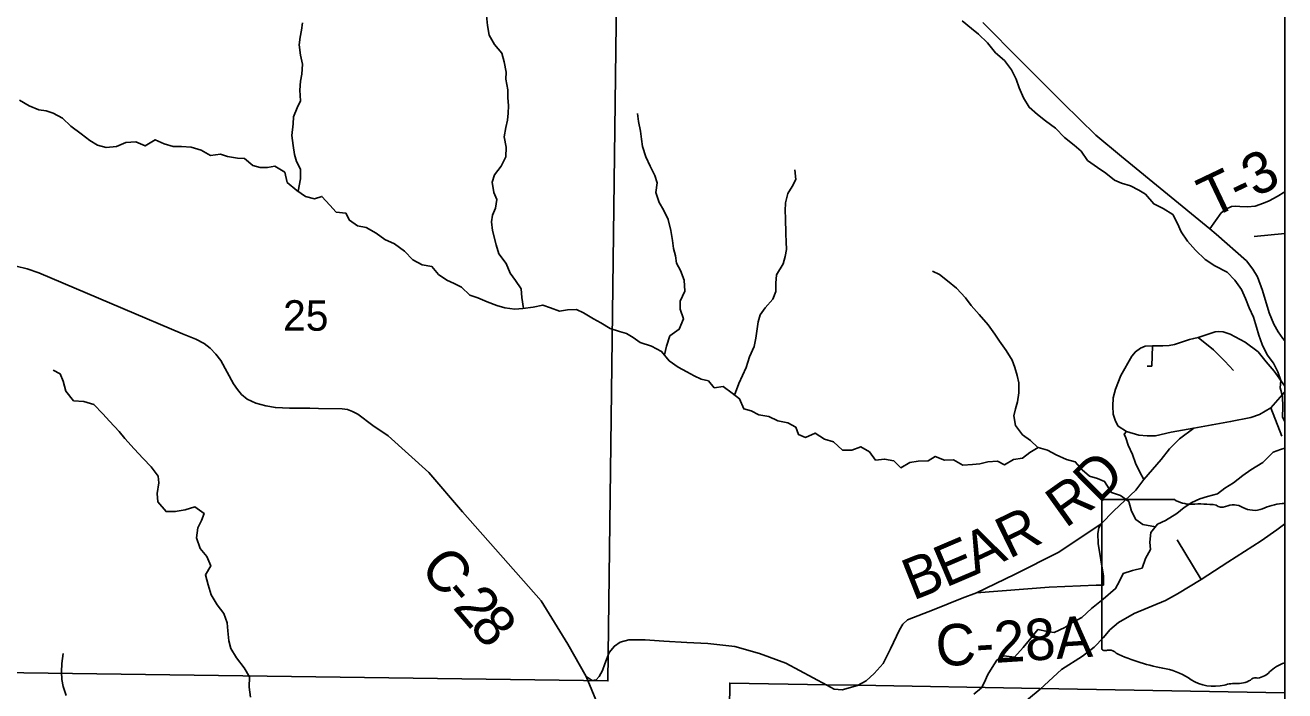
# Model space of a CAD drawing. Extents: x -3.6 to 34, y 0 to 32.8.
# Drawn here: x 1.441 to 3.17, y 28.937 to 29.85 of the extents above; entities that cross this region are included whole.
import ezdxf

# ---------------------------------------------------------------- set-up
doc = ezdxf.new("R2010")
doc.units = 0
for name, color, linetype in [('GM_X_Corporation', 7, 'Continuous'), ('GM_X_County_Road', 7, 'Continuous'), ('GM_X_County_Road_Text', 7, 'Continuous'), ('GM_X_Minor_River', 7, 'Continuous'), ('GM_X_Section_Text', 7, 'Continuous'), ('GM_X_State_Location', 7, 'Continuous'), ('GM_X_State_Route', 7, 'Continuous'), ('GM_X_State_Shield', 7, 'Continuous'), ('GM_X_Township_Road', 7, 'Continuous'), ('GM_X_Township_Road_Text', 7, 'Continuous'), ('SH_Data', 7, 'Continuous')]:
    doc.layers.add(name, color=color, linetype=linetype)

msp = doc.modelspace()

# ---------------------------------------------------------------- linework, layer by layer
at = {"layer": 'GM_X_Corporation'}
for points in [[(3.1705, 28.9337), (3.1705, 32.8429), (-3.6295, 32.8429), (-3.6295, 26.0429), (2.3706, 26.0429), (2.3712, 26.0804), (2.3716, 26.1248), (2.3732, 26.2253), (2.3789, 26.6097), (2.3911, 27.5117), (2.3952, 27.9336), (2.3997, 28.282), (2.4082, 28.9473), (2.5416, 28.945), (2.5837, 28.9442), (2.8343, 28.9397)], [(2.2535, 29.9602), (2.2411, 28.9502), (1.4051, 28.9619), (1.2386, 28.9647), (1.2483, 29.9822)], [(2.3706, 26.0429), (3.1705, 26.0429), (3.1705, 28.9337), (2.8343, 28.9397), (2.5837, 28.9442), (2.5416, 28.945), (2.4082, 28.9473), (2.3997, 28.282), (2.3952, 27.9336), (2.3911, 27.5117), (2.3789, 26.6097), (2.3732, 26.2253), (2.3716, 26.1248), (2.3712, 26.0804)], [(2.3706, 26.0429), (3.1705, 26.0429), (3.1705, 28.9337), (2.8343, 28.9397), (2.5837, 28.9442), (2.5416, 28.945), (2.4082, 28.9473), (2.3997, 28.282), (2.3952, 27.9336), (2.3911, 27.5117), (2.3789, 26.6097), (2.3732, 26.2253), (2.3716, 26.1248), (2.3712, 26.0804)]]:
    msp.add_lwpolyline(points, close=True, dxfattribs=at)
msp.add_lwpolyline([(-2.8635, 26.0429), (2.3706, 26.0429), (2.3712, 26.0804), (2.3716, 26.1248), (2.3732, 26.2253), (2.3789, 26.6097), (2.3911, 27.5117), (2.3952, 27.9336), (2.3997, 28.282), (2.4082, 28.9473), (2.5416, 28.945), (2.5837, 28.9442), (2.8343, 28.9397), (3.1705, 28.9337), (3.1705, 30.458), (3.0419, 30.4594), (1.7819, 30.4857), (1.2437, 30.4948), (0.4055, 30.5105), (0.3556, 30.5115), (0.2578, 30.5133), (0.2583, 30.5905), (-0.398, 30.5946), (-0.453, 30.5952)], dxfattribs=at)
at = {"layer": 'GM_X_County_Road'}
msp.add_line((2.9114, 29.0816), (2.9213, 29.0818), dxfattribs=at)
for points in [[(3.1705, 29.3468), (3.1514, 29.3247), (3.1356, 29.3156), (3.1236, 29.3116), (3.0961, 29.306), (3.0706, 29.3017), (3.0455, 29.2968), (3.026, 29.2822), (3.0121, 29.2687), (3.0009, 29.2541), (2.9767, 29.2268), (2.9658, 29.2119), (2.9358, 29.1834), (2.9183, 29.1659), (2.8604, 29.1267), (2.7993, 29.0964), (2.7472, 29.0711), (2.7273, 29.0639), (2.6891, 29.0481), (2.6526, 29.0339), (2.6461, 29.028), (2.6412, 29.0205), (2.629, 28.9944), (2.6189, 28.9739), (2.6064, 28.9604), (2.5956, 28.9503), (2.5839, 28.9437), (2.5627, 28.9378), (2.5518, 28.9388), (2.5418, 28.9445), (2.4855, 28.9746), (2.4493, 28.9878), (2.4153, 28.9972), (2.3781, 29.0014), (2.3494, 29.003), (2.3176, 29.0048), (2.2921, 29.0064), (2.2698, 29.0064), (2.2579, 29.0034), (2.25, 28.9981), (2.2426, 28.989), (2.2367, 28.9736), (2.2337, 28.9644), (2.229, 28.9562), (2.2247, 28.9518), (2.2193, 28.951), (2.2112, 28.9561), (2.1861, 29.0005), (2.1493, 29.0599), (2.0415, 29.1821), (1.9951, 29.2364), (1.9392, 29.2865), (1.9182, 29.3005), (1.8978, 29.3163), (1.8904, 29.3201), (1.8835, 29.3228), (1.8763, 29.3237), (1.8435, 29.3239), (1.8317, 29.3243), (1.8036, 29.3245), (1.7844, 29.3253), (1.7712, 29.3275), (1.7574, 29.3313), (1.7456, 29.337), (1.7381, 29.3432), (1.7323, 29.3502), (1.727, 29.3579), (1.7093, 29.3897), (1.7026, 29.3986), (1.6948, 29.4069), (1.6868, 29.413), (1.6753, 29.4191), (1.6567, 29.4265), (1.575, 29.4611), (1.4595, 29.5103), (1.4436, 29.5156), (1.4286, 29.5194)], [(2.7472, 29.0711), (2.8471, 29.0789), (2.9114, 29.0816)]]:
    msp.add_lwpolyline(points, dxfattribs=at)
at = {"layer": 'GM_X_Minor_River'}
for points in [[(1.8157, 29.622), (1.8189, 29.6389), (1.8187, 29.6526), (1.8133, 29.6627), (1.8105, 29.6725), (1.8087, 29.685), (1.807, 29.6987), (1.8087, 29.7146), (1.8093, 29.7241), (1.8144, 29.7367), (1.8188, 29.7463), (1.8178, 29.7606), (1.8191, 29.7732), (1.8205, 29.7827), (1.8218, 29.7964), (1.819, 29.8088), (1.8172, 29.8232), (1.8186, 29.8335), (1.8203, 29.843), (1.8217, 29.8533)], [(2.1249, 29.4612), (2.1226, 29.4762), (2.122, 29.4883), (2.1139, 29.4996), (2.1066, 29.5097), (2.1015, 29.5229), (2.0914, 29.536), (2.0874, 29.5485), (2.0826, 29.5681), (2.0813, 29.5799), (2.0827, 29.5894), (2.0867, 29.5989), (2.0884, 29.6107), (2.0844, 29.6205), (2.0823, 29.6345), (2.0852, 29.6444), (2.0945, 29.6563), (2.1007, 29.6693), (2.1013, 29.6826), (2.0984, 29.6966), (2.1009, 29.7095), (2.103, 29.7194), (2.104, 29.7293), (2.1046, 29.7395), (2.1037, 29.7505), (2.1035, 29.7611), (2.101, 29.7759), (2.1012, 29.7854), (2.0987, 29.7998), (2.0952, 29.8115), (2.0855, 29.8235), (2.0781, 29.8362), (2.0757, 29.8495), (2.0743, 29.8631)], [(3.1705, 29.3059), (3.1672, 29.3124), (3.1678, 29.326), (3.1675, 29.3408), (3.1643, 29.3525), (3.1649, 29.3624), (3.161, 29.3741), (3.1551, 29.3861), (3.1462, 29.3978), (3.1396, 29.4117), (3.1349, 29.4245), (3.1317, 29.4355), (3.1277, 29.4495), (3.1214, 29.4623), (3.1163, 29.4747), (3.1108, 29.4871), (3.1019, 29.5003), (3.0915, 29.5111), (3.0744, 29.5196), (3.061, 29.5285), (3.0479, 29.5412), (3.0368, 29.5535), (3.0283, 29.5663), (3.0232, 29.578), (3.0165, 29.5904), (3.0035, 29.5986), (2.9906, 29.6048), (2.9794, 29.6179), (2.9699, 29.6235), (2.9584, 29.6294), (2.9463, 29.6333), (2.9364, 29.6374), (2.9245, 29.6471), (2.9134, 29.6545), (2.8996, 29.6645), (2.8907, 29.6773), (2.8811, 29.6855), (2.8681, 29.6959), (2.8554, 29.7086), (2.842, 29.7186), (2.8309, 29.7276), (2.8194, 29.7373), (2.8116, 29.7504), (2.8058, 29.764), (2.8014, 29.7761), (2.7952, 29.7889), (2.7855, 29.8013), (2.7732, 29.8121), (2.7621, 29.8256), (2.7498, 29.8375), (2.7402, 29.8453), (2.7275, 29.8561)], [(1.8592, 29.6031), (1.8484, 29.6151), (1.8379, 29.6119), (1.8257, 29.6151), (1.8139, 29.6233), (1.8008, 29.6341), (1.7972, 29.6481), (1.7838, 29.6566), (1.7736, 29.6549), (1.7634, 29.6548), (1.7535, 29.6573), (1.742, 29.667), (1.7322, 29.6676), (1.7185, 29.6696), (1.709, 29.6729), (1.6954, 29.6712), (1.6825, 29.6786), (1.6688, 29.6825), (1.6555, 29.6835), (1.6442, 29.6837), (1.6316, 29.6873), (1.6194, 29.6928), (1.6056, 29.6842), (1.593, 29.6897), (1.579, 29.6888), (1.5662, 29.6836), (1.5522, 29.6819), (1.5401, 29.6855), (1.5298, 29.6918), (1.5175, 29.7007), (1.5037, 29.7115), (1.4922, 29.7224), (1.4792, 29.7294), (1.4697, 29.7326), (1.4595, 29.734), (1.4462, 29.7391), (1.4332, 29.7469)], [(2.3186, 29.3977), (2.3215, 29.4093), (2.3262, 29.4235), (2.3389, 29.4327), (2.3448, 29.4472), (2.3404, 29.4605), (2.3403, 29.4711), (2.3465, 29.4852), (2.3459, 29.5), (2.3407, 29.5132), (2.3353, 29.5233), (2.3336, 29.5336), (2.3312, 29.5434), (2.3299, 29.5544), (2.3274, 29.5684), (2.3238, 29.5831), (2.3175, 29.5967), (2.3113, 29.6068), (2.3066, 29.6204), (2.3086, 29.6337), (2.3055, 29.6435), (2.2992, 29.6567), (2.2933, 29.6691), (2.2886, 29.6835), (2.2873, 29.6937), (2.2856, 29.7047), (2.2828, 29.7179), (2.2818, 29.7289)], [(2.4149, 29.3424), (2.4207, 29.3581), (2.4309, 29.3803), (2.4356, 29.3951), (2.4418, 29.4092), (2.444, 29.4203), (2.4457, 29.4302), (2.4474, 29.4431), (2.4503, 29.4526), (2.4569, 29.4622), (2.4673, 29.4741), (2.4714, 29.4844), (2.4716, 29.4958), (2.4725, 29.5076), (2.4817, 29.5225), (2.4846, 29.5324), (2.4864, 29.5423), (2.4858, 29.5525), (2.4853, 29.5635), (2.485, 29.5851), (2.4844, 29.595), (2.485, 29.6064), (2.4882, 29.6189), (2.4941, 29.6285), (2.4989, 29.6384), (2.4979, 29.6513)], [(2.993, 29.1618), (2.9757, 29.165), (2.9658, 29.1716), (2.9599, 29.1833), (2.9563, 29.1962), (2.9448, 29.2047), (2.9323, 29.2087), (2.923, 29.2237), (2.9131, 29.2278), (2.9021, 29.231), (2.8921, 29.24), (2.8828, 29.2508), (2.8707, 29.254), (2.8566, 29.2603), (2.8444, 29.2666), (2.8318, 29.2705), (2.8202, 29.2635), (2.8105, 29.2558), (2.798, 29.2541), (2.7856, 29.2467), (2.7761, 29.2519), (2.7629, 29.2509), (2.7519, 29.2481), (2.7417, 29.2472), (2.7285, 29.2462), (2.7155, 29.2536), (2.7034, 29.2531), (2.6905, 29.2582), (2.6807, 29.2523), (2.6671, 29.2518), (2.6554, 29.2501), (2.643, 29.2427), (2.6334, 29.252), (2.6209, 29.2545), (2.6085, 29.2532), (2.6003, 29.2644), (2.5881, 29.2715), (2.5761, 29.2667), (2.5632, 29.2669), (2.5509, 29.2781), (2.5384, 29.2817), (2.5254, 29.2902), (2.5122, 29.2844), (2.5027, 29.2884), (2.4992, 29.2982), (2.4881, 29.3041), (2.4744, 29.3069), (2.4619, 29.3132), (2.4482, 29.3153), (2.4375, 29.3208), (2.4276, 29.3237), (2.4218, 29.3373), (2.4114, 29.3451), (2.3992, 29.354), (2.3871, 29.3523), (2.379, 29.362), (2.3691, 29.3642), (2.3596, 29.3686), (2.3493, 29.3745), (2.3375, 29.3808), (2.3252, 29.3893), (2.3148, 29.4024), (2.3007, 29.4094), (2.2855, 29.4145), (2.2759, 29.4216), (2.2664, 29.4271), (2.2569, 29.4296), (2.2443, 29.4336), (2.2313, 29.4414), (2.221, 29.4469), (2.2077, 29.4551), (2.1981, 29.4599), (2.1853, 29.4593), (2.1747, 29.4576), (2.1622, 29.462), (2.1515, 29.466), (2.1383, 29.4631), (2.124, 29.461), (2.1134, 29.4605), (2.0993, 29.4622), (2.0883, 29.4654), (2.0754, 29.4705), (2.0624, 29.476), (2.0514, 29.4797), (2.0399, 29.4905), (2.03, 29.4953), (2.0197, 29.5), (2.0086, 29.5078), (1.9993, 29.5187), (1.9861, 29.5212), (1.9731, 29.5282), (1.9616, 29.5398), (1.9478, 29.5498), (1.9348, 29.5561), (1.923, 29.5646), (1.9092, 29.5724), (1.8971, 29.5745), (1.8864, 29.5823), (1.8813, 29.592), (1.8677, 29.5934), (1.8592, 29.6031)], [(2.8314, 29.2703), (2.8211, 29.2802), (2.8104, 29.288), (2.8007, 29.3008), (2.7986, 29.314), (2.8007, 29.3236), (2.8036, 29.3331), (2.8053, 29.3456), (2.8051, 29.3593), (2.8031, 29.3695), (2.7999, 29.3801), (2.7959, 29.3902), (2.7878, 29.4038), (2.7789, 29.4162), (2.7723, 29.4259), (2.763, 29.4387), (2.7507, 29.4529), (2.7396, 29.4653), (2.7318, 29.4758), (2.7195, 29.4889), (2.7073, 29.4993), (2.6961, 29.5079), (2.6866, 29.5126)], [(1.7503, 28.9281), (1.7482, 28.9418), (1.7487, 28.9558), (1.7417, 28.9682), (1.7309, 28.9817), (1.7232, 28.9949), (1.7207, 29.0051), (1.719, 29.0191), (1.7181, 29.0301), (1.7134, 29.0425), (1.7045, 29.0545), (1.6963, 29.0681), (1.6919, 29.082), (1.6883, 29.0956), (1.6957, 29.1079), (1.6902, 29.1211), (1.681, 29.1319), (1.6762, 29.1467), (1.6779, 29.1603), (1.683, 29.1703), (1.6867, 29.1798), (1.674, 29.1891), (1.6605, 29.1851), (1.6469, 29.1826), (1.6344, 29.1825), (1.6232, 29.1959), (1.6219, 29.2073), (1.6243, 29.2218), (1.6234, 29.2312), (1.6138, 29.244), (1.603, 29.2552), (1.5903, 29.2687), (1.5776, 29.2829), (1.5699, 29.2926), (1.5565, 29.3065), (1.5476, 29.3166), (1.5349, 29.3293), (1.5212, 29.3336), (1.5072, 29.3345), (1.4968, 29.3477), (1.4932, 29.3616), (1.4889, 29.3714), (1.4793, 29.3766)], [(3.1705, 29.2696), (3.1645, 29.2676), (3.1547, 29.264), (3.1405, 29.2501), (3.1237, 29.24), (3.1128, 29.2319), (3.1001, 29.2222), (3.0881, 29.2148), (3.078, 29.2067), (3.0644, 29.2031), (3.0539, 29.1999), (3.0426, 29.1952), (3.0321, 29.1882), (3.0224, 29.1797), (3.0067, 29.1704), (2.9958, 29.1653), (2.9865, 29.1538), (2.9852, 29.1408), (2.9861, 29.1306), (2.9791, 29.1184), (2.9744, 29.105), (2.9615, 29.1018), (2.9484, 29.0974), (2.9436, 29.0871), (2.9381, 29.0768), (2.9209, 29.0625), (2.9052, 29.0497), (2.8918, 29.037), (2.8782, 29.03), (2.8685, 29.0234), (2.8539, 29.0167), (2.8444, 29.0181), (2.8315, 29.0209), (2.8222, 29.0094), (2.811, 28.996), (2.7995, 28.9829), (2.7847, 28.9846), (2.775, 28.9787), (2.7687, 28.9688), (2.7628, 28.9588), (2.7576, 28.9478), (2.7539, 28.9409)], [(1.4971, 28.9304), (1.4931, 28.9425), (1.4911, 28.9523), (1.4909, 28.9625), (1.4911, 28.9739), (1.4932, 28.9876)], [(2.7436, 28.9322), (2.7539, 28.9409)]]:
    msp.add_lwpolyline(points, dxfattribs=at)
at = {"layer": 'GM_X_State_Route'}
for points in [[(3.1705, 29.4169), (3.1679, 29.42), (3.1612, 29.4292), (3.1555, 29.4395), (3.1489, 29.4552), (3.1399, 29.4858), (3.1328, 29.5045), (3.1266, 29.5152), (3.1177, 29.5268), (3.0762, 29.5633), (3.0677, 29.5707), (2.9462, 29.6699), (2.9109, 29.6991), (2.8663, 29.7429), (2.8077, 29.8013), (2.7556, 29.8537)], [(2.8345, 28.9391), (2.8637, 28.9659), (2.8928, 28.9842), (2.9088, 28.9967), (2.9216, 29.0098), (2.9302, 29.0201), (2.9421, 29.0305), (2.9635, 29.0427), (3.0066, 29.0606), (3.023, 29.0696), (3.0557, 29.0893), (3.0924, 29.1132), (3.1378, 29.1425), (3.1593, 29.1577), (3.1705, 29.1656)], [(2.7996, 28.9101), (2.8345, 28.9391)]]:
    msp.add_lwpolyline(points, dxfattribs=at)
at = {"layer": 'GM_X_State_Shield'}
for p, q in [((3.0189, 29.199), (2.9223, 29.199)), ((2.9191, 29.1955), (2.9191, 28.9954)), ((3.1705, 28.975), (3.1705, 29.194))]:
    msp.add_line(p, q, dxfattribs=at)
for centre, major_axis, start_param, end_param in [((2.9229, 29.196), (0.00382, 0), 1.727492, 3.291633), ((3.0418, 29.2222), (0.037, 0), 4.042888, 4.731792), ((3.0541, 29.0866), (0.133, 0), 1.404758, 1.657859), ((3.0843, 29.197), (0.0107, 0), 3.836095, 5.185415), ((3.1, 29.1739), (0.0222, 0), 0.950623, 2.079405), ((3.1287, 29.2056), (0.0267, 0), 4.08156, 5.145723), ((3.1758, 29.1379), (0.0703, 0), 1.699012, 2.107814), ((3.1313, 29.4718), (0.3495, 0), 4.814394, 4.824795), ((2.9229, 28.995), (0.00385, 0), 2.993084, 4.5083), ((2.9235, 29.0155), (0.0294, 0), 4.665946, 4.897461), ((2.9295, 28.9839), (0.0106, 0), 0.519207, 1.627899), ((3.0633, 29.1637), (0.2524, 0), 4.195997, 4.488961), ((3.1877, 28.9392), (0.0479, 0), 1.939048, 2.488434), ((2.9881, 28.9055), (0.079, 0), 0.823519, 1.323587), ((3.1302, 28.9485), (0.00752, 0), 1.147584, 2.315152), ((3.127, 28.976), (0.0282, 0), 4.937069, 5.64225), ((3.0735, 28.9829), (0.0501, 0), 4.026481, 4.996735), ((3.1024, 28.9137), (0.0412, 0), 1.495662, 1.94098), ((3.1061, 28.9679), (0.0267, 0), 4.691044, 5.507374)]:
    msp.add_ellipse(centre, major_axis=major_axis, ratio=0.8, start_param=start_param, end_param=end_param, dxfattribs=at)
at = {"layer": 'GM_X_Township_Road'}
for p, q in [((3.1705, 29.5642), (3.1284, 29.5601)), ((3.1666, 29.286), (3.1514, 29.3247)), ((3.0557, 29.0893), (3.0225, 29.1438))]:
    msp.add_line(p, q, dxfattribs=at)
for points in [[(3.0677, 29.5707), (3.0831, 29.5925), (3.0894, 29.5975), (3.0971, 29.6013), (3.1026, 29.6018), (3.1085, 29.6013), (3.1191, 29.6007), (3.1297, 29.6018), (3.1411, 29.6057), (3.1491, 29.609), (3.1602, 29.6148), (3.1705, 29.6214)], [(3.0455, 29.2968), (3.0142, 29.2915), (2.9931, 29.2867), (2.9816, 29.2865), (2.9702, 29.2875), (2.9533, 29.2926), (2.9415, 29.2999), (2.9378, 29.3068), (2.9349, 29.316), (2.9343, 29.3273), (2.9348, 29.3386), (2.9379, 29.3505), (2.9453, 29.3693), (2.9603, 29.3959), (2.9653, 29.4018), (2.9725, 29.407), (2.9788, 29.4095), (2.9886, 29.4099), (3.0029, 29.4101), (3.0115, 29.4106), (3.0191, 29.412), (3.0243, 29.4135), (3.0396, 29.4188), (3.0455, 29.4202), (3.0516, 29.4216), (3.075, 29.4292), (3.0799, 29.4295), (3.0858, 29.4292), (3.0956, 29.426), (3.1159, 29.415), (3.1338, 29.4016), (3.1451, 29.3882), (3.156, 29.3754), (3.1705, 29.3545)], [(3.0998, 29.3761), (3.0883, 29.389), (3.0726, 29.4045), (3.0516, 29.4216)], [(2.9817, 29.3823), (2.9877, 29.3823), (2.9886, 29.4099)], [(2.9767, 29.2268), (2.9708, 29.2376), (2.9653, 29.2492), (2.9614, 29.2608), (2.9553, 29.2738), (2.952, 29.2836), (2.95, 29.2886), (2.9533, 29.2926)], [(2.9213, 29.0818), (2.9217, 29.0941), (2.9141, 29.1387), (2.9139, 29.1523), (2.9153, 29.1602), (2.9183, 29.1659)], [(2.2112, 28.9561), (2.2367, 28.8943), (2.2565, 28.8547), (2.2672, 28.8262), (2.2846, 28.7852), (2.2881, 28.7671), (2.2888, 28.7081), (2.2774, 28.6424), (2.2812, 28.5756), (2.2741, 28.5386), (2.2578, 28.5029), (2.2549, 28.4915), (2.2513, 28.4756), (2.2597, 28.4398), (2.2593, 28.4174), (2.261, 28.4022), (2.2681, 28.3872), (2.2764, 28.376), (2.2905, 28.3608), (2.3111, 28.3286)]]:
    msp.add_lwpolyline(points, dxfattribs=at)
at = {"layer": 'SH_Data'}
msp.add_line((3.1705, 32.8429), (3.1705, 26.0429), dxfattribs=at)

# ---------------------------------------------------------------- texts
at = {"layer": 'GM_X_County_Road_Text'}
for s, height, rotation, p in [('D', 0.0568, 44.8007, (2.9146, 29.1924)), ('R', 0.0568, 35.6146, (2.8692, 29.1589)), ('R', 0.0568, 25.9888, (2.7918, 29.1172)), ('E', 0.0568, 23.0721, (2.7046, 29.0779)), ('A', 0.0568, 25.2482, (2.7459, 29.0955)), ('C', 0.0568, 310.7431, (1.981, 29.1037)), ('B', 0.0568, 21.6666, (2.6599, 29.0601)), ('-', 0.0568, 310.7241, (2.0115, 29.0683)), ('2', 0.0568, 310.6261, (2.0267, 29.0507)), ('8', 0.0568, 310.1571, (2.0494, 29.0242)), ('C-28A', 0.05682, 3.6367, (2.6928, 28.9698))]:
    msp.add_text(s, height=height, rotation=rotation, dxfattribs=at).set_placement(p)
at = {"layer": 'GM_X_Section_Text'}
msp.add_text('25', height=0.04186, rotation=0, dxfattribs=at).set_placement((1.795, 29.4307))
at = {"layer": 'GM_X_State_Location'}
for s in ['s', 'r']:
    msp.add_text(s, height=0.000189, dxfattribs=at).set_placement((3.0802, 29.0822))
msp.add_text('164', height=0.000189, rotation=0, dxfattribs=at).set_placement((3.0133, 29.0684))
at = {"layer": 'GM_X_Township_Road_Text'}
for s, rotation, p in [('3', 27.2211, (3.1301, 29.613)), ('T', 25.4984, (3.0692, 29.584)), ('-', 25.4366, (3.1075, 29.6023))]:
    msp.add_text(s, height=0.0568, rotation=rotation, dxfattribs=at).set_placement(p)

doc.saveas('drawing.dxf')
